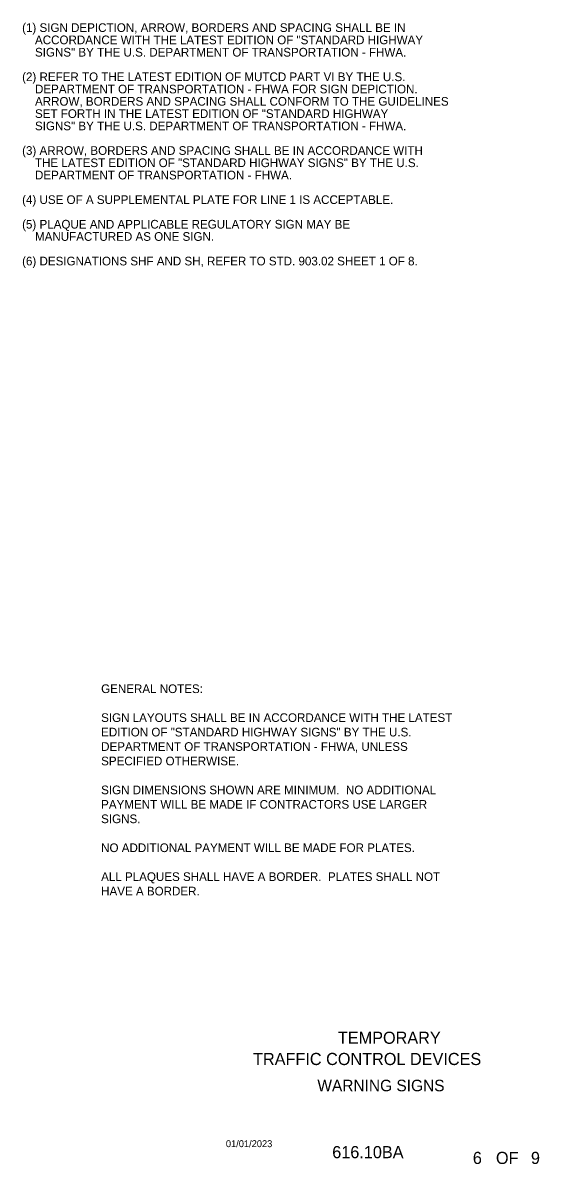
# Model space of a CAD drawing. Extents: x -439.1 to -408.3, y -458.1 to -437.7.
# Drawn here: x -417.21 to -408.28, y -457.85 to -438.11 of the extents above; entities that cross this region are included whole.
import ezdxf

# ---------------------------------------------------------------- set-up
doc = ezdxf.new("R2010")
doc.units = 0
for name, color, linetype in [('Common-Notes', 7, 'Continuous'), ('Level 4', 7, 'Continuous'), ('Level 45', 7, 'Continuous')]:
    doc.layers.add(name, color=color, linetype=linetype)

msp = doc.modelspace()

# ---------------------------------------------------------------- texts
at = {"layer": 'Common-Notes'}
for s, p in [('TEMPORARY', (-411.763, -455.765)), ('TRAFFIC CONTROL DEVICES', (-413.231, -456.132)), ('616.10BA', (-411.861, -457.743)), ('6', (-409.429, -457.843)), ('OF', (-409.029, -457.843)), ('9', (-408.424, -457.843))]:
    msp.add_text(s, height=0.21, dxfattribs=at).set_placement(p)
at = {"layer": 'Level 4'}
for s, height, p in [('(1) SIGN DEPICTION, ARROW, BORDERS AND SPACING SHALL BE IN ', 0.15, (-417.226, -438.266)), ('    ACCORDANCE WITH THE LATEST EDITION OF "STANDARD HIGHWAY ', 0.15, (-417.226, -438.478)), ('    SIGNS" BY THE U.S. DEPARTMENT OF TRANSPORTATION - FHWA.', 0.15, (-417.226, -438.691)), ('(2) REFER TO THE LATEST EDITION OF MUTCD PART VI BY THE U.S. ', 0.15, (-417.226, -439.116)), ('    DEPARTMENT OF TRANSPORTATION - FHWA FOR SIGN DEPICTION. ', 0.15, (-417.226, -439.328)), ('    ARROW, BORDERS AND SPACING SHALL CONFORM TO THE GUIDELINES ', 0.15, (-417.226, -439.541)), ('    SET FORTH IN THE LATEST EDITION OF "STANDARD HIGHWAY ', 0.15, (-417.226, -439.753)), ('    SIGNS" BY THE U.S. DEPARTMENT OF TRANSPORTATION - FHWA.', 0.15, (-417.226, -439.966)), ('(3) ARROW, BORDERS AND SPACING SHALL BE IN ACCORDANCE WITH ', 0.15, (-417.226, -440.391)), ('    THE LATEST EDITION OF "STANDARD HIGHWAY SIGNS" BY THE U.S. ', 0.15, (-417.226, -440.603)), ('    DEPARTMENT OF TRANSPORTATION - FHWA.', 0.15, (-417.226, -440.816)), ('(4) USE OF A SUPPLEMENTAL PLATE FOR LINE 1 IS ACCEPTABLE.', 0.15, (-417.226, -441.241)), ('(5) PLAQUE AND APPLICABLE REGULATORY SIGN MAY BE ', 0.15, (-417.226, -441.666)), ('    MANUFACTURED AS ONE SIGN.', 0.15, (-417.226, -441.878)), ('(6) DESIGNATIONS SHF AND SH, REFER TO STD. 903.02 SHEET 1 OF 8.', 0.15, (-417.226, -442.303)), ('WARNING SIGNS', 0.2, (-412.118, -456.586)), ('01/01/2023', 0.12, (-413.701, -457.552))]:
    msp.add_text(s, height=height, dxfattribs=at).set_placement(p)
at = {"layer": 'Level 45'}
for s, p in [('GENERAL NOTES:', (-415.859, -449.699)), ('SIGN LAYOUTS SHALL BE IN ACCORDANCE WITH THE LATEST ', (-415.859, -450.199)), ('EDITION OF "STANDARD HIGHWAY SIGNS" BY THE U.S. ', (-415.859, -450.449)), ('DEPARTMENT OF TRANSPORTATION - FHWA, UNLESS ', (-415.859, -450.699)), ('SPECIFIED OTHERWISE.', (-415.859, -450.949)), ('SIGN DIMENSIONS SHOWN ARE MINIMUM.  NO ADDITIONAL ', (-415.859, -451.449)), ('PAYMENT WILL BE MADE IF CONTRACTORS USE LARGER ', (-415.859, -451.699)), ('SIGNS.', (-415.859, -451.949)), ('NO ADDITIONAL PAYMENT WILL BE MADE FOR PLATES. ', (-415.859, -452.449)), ('ALL PLAQUES SHALL HAVE A BORDER.  PLATES SHALL NOT ', (-415.859, -452.949)), ('HAVE A BORDER.', (-415.859, -453.199))]:
    msp.add_text(s, height=0.15, dxfattribs=at).set_placement(p)

doc.saveas('drawing.dxf')
